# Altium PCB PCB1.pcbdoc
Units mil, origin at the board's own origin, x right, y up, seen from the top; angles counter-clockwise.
Board outline 1908.46 x 3230 mil, 2 copper layers (Top Layer, Bottom Layer); 17 components, 32 nets, 150 pads, 4 vias.
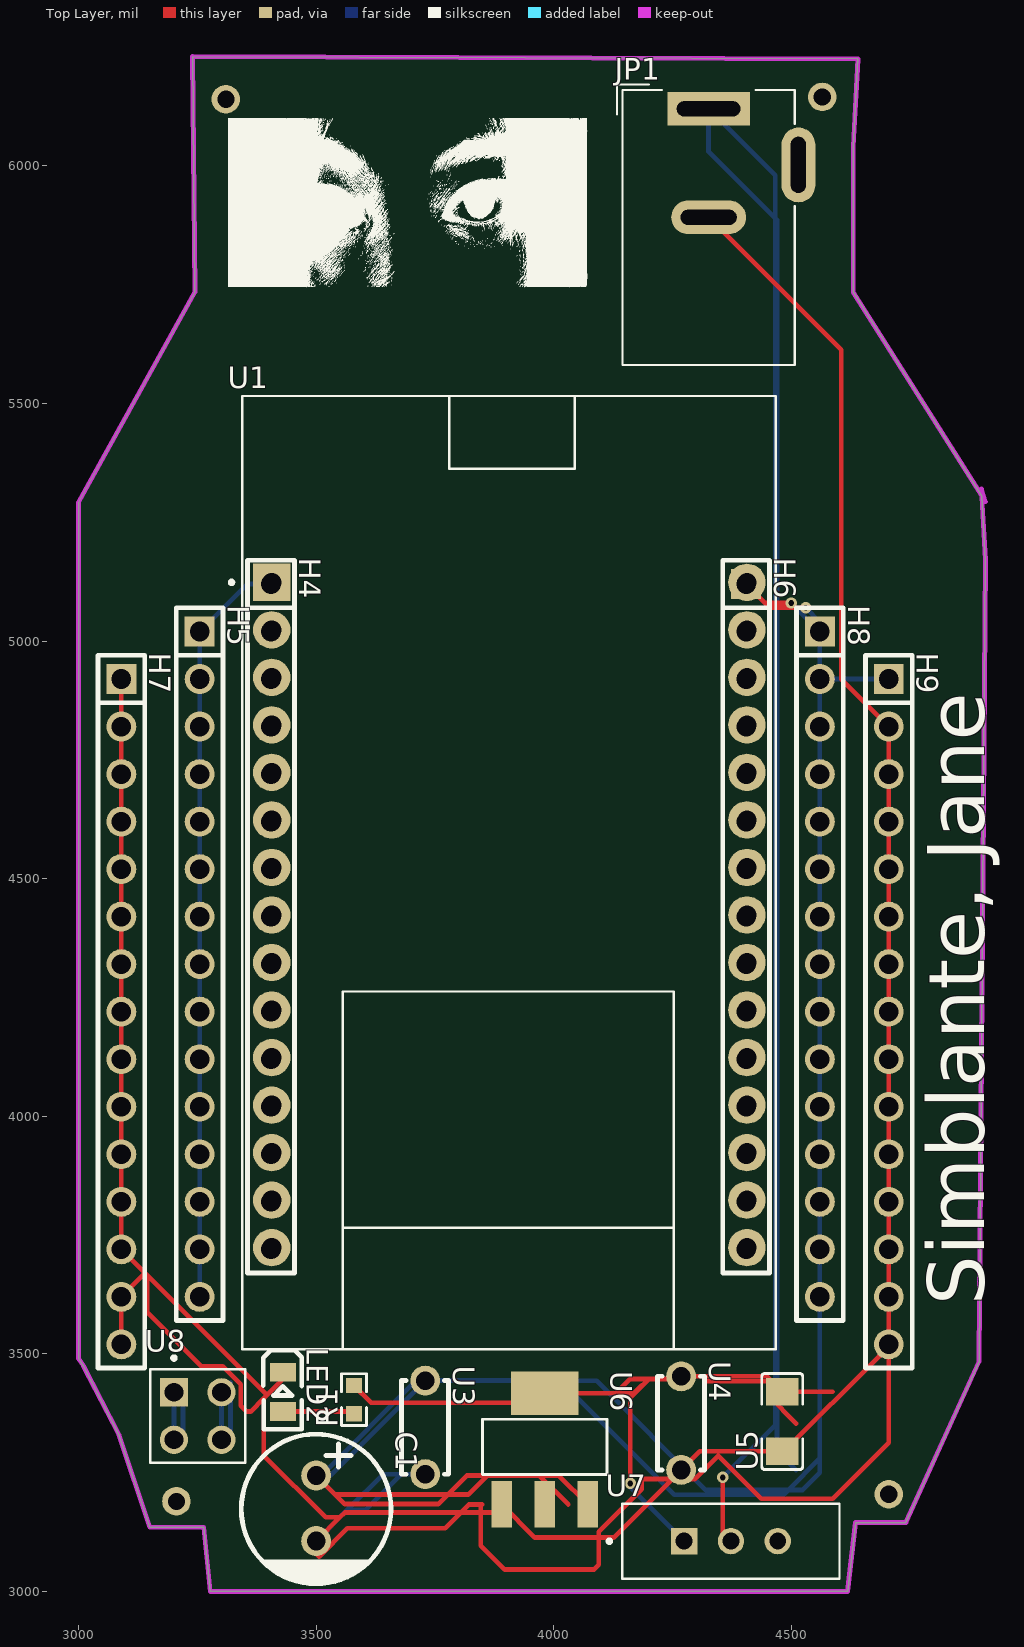
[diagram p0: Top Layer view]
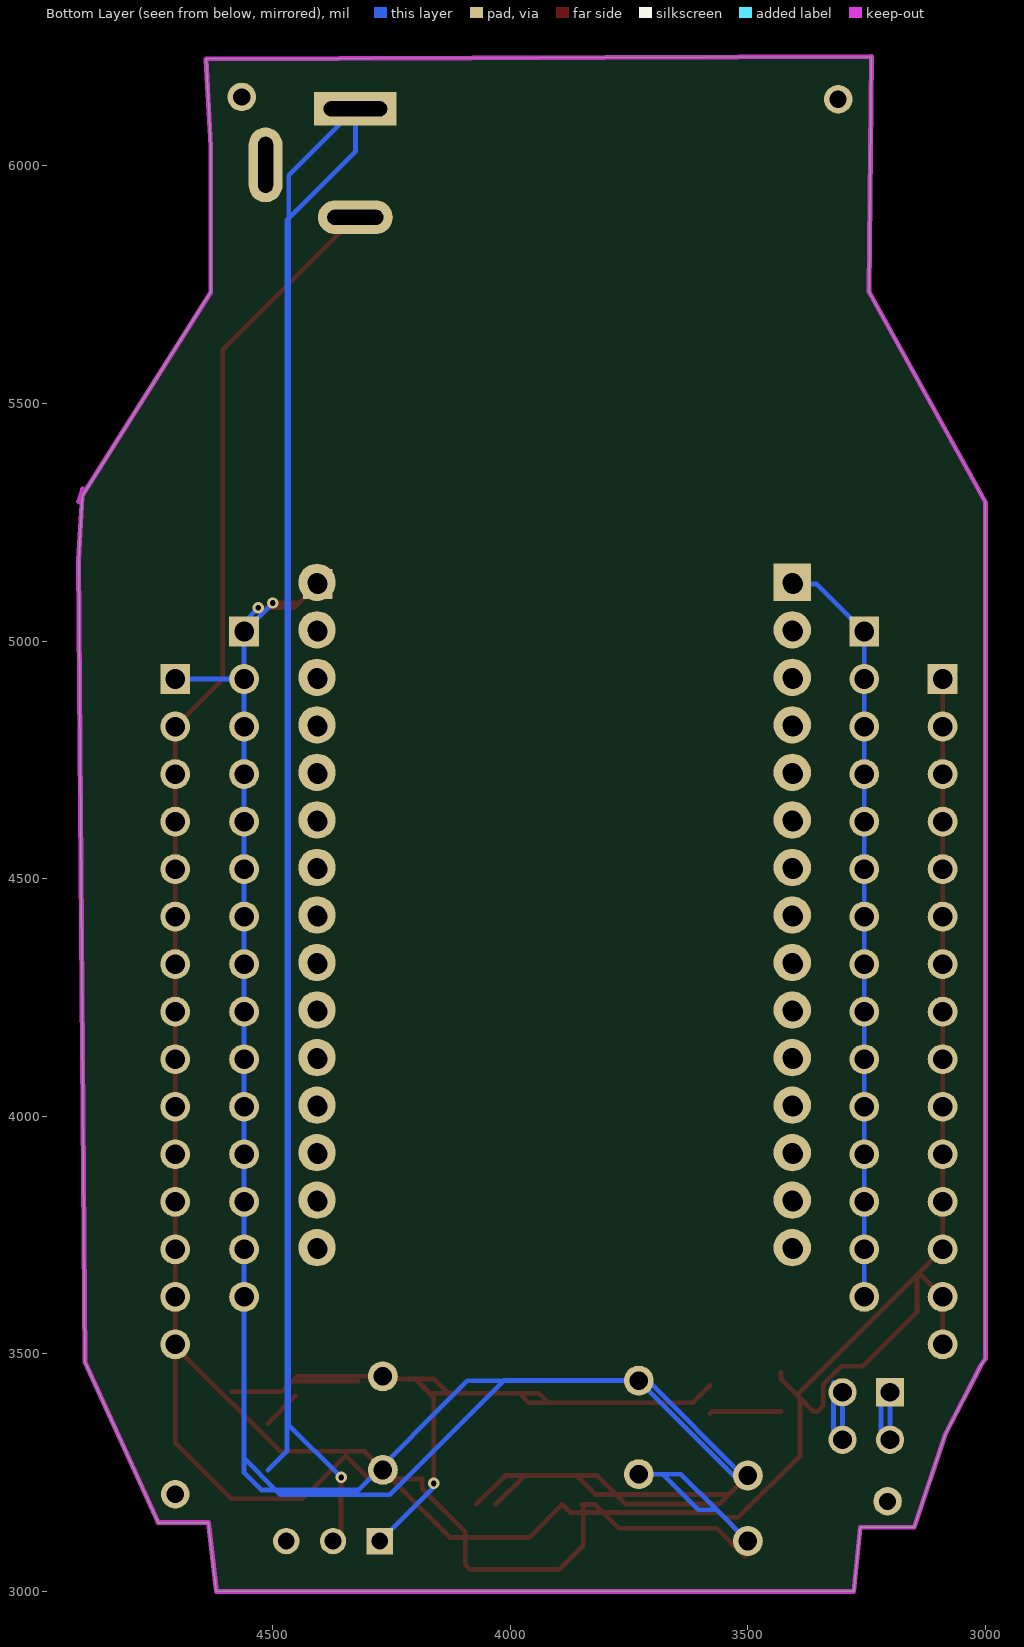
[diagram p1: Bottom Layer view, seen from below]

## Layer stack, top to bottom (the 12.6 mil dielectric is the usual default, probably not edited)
Top Layer: signal copper (thickness not stored)
Dielectric: dielectric 12.6, FR-4, Dk 4.8
Bottom Layer: signal copper (thickness not stored)

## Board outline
4908.46,5170.47 4900.84,5305.25 4630,5734.75 4630,6040 4640,6225 3240,6230 3245,5734.75 3000,5292.06 3000,3490 3010,3475 3085,3330 3149.93,3135 3263.45,3135 3277.42,3000 4618.27,3000 4635,3145 4741.01,3145 4895,3484.09

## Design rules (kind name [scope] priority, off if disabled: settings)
BoardOutlineClearance copperThickness1oz [All] p0: genericclearance=10 ignorepadtopadclearanceinfootprint=FALSE except(0: Arc-SplitContinuation Track-SplitContinuation SMDPad-SplitContinuation THPad-SplitContinuation Via-SplitContinuation Fill-SplitContinuation Poly-SplitContinuation Region-SplitContinuation Text-SplitContinuation; 6: Track-CutoutEdge SMDPad-CutoutEdge THPad-CutoutEdge Via-CutoutEdge Region-CutoutEdge; 11.8: Track-OutlineEdge SMDPad-OutlineEdge THPad-OutlineEdge Via-OutlineEdge Fill-OutlineEdge Region-OutlineEdge Poly-OutlineEdge Text-OutlineEdge Fill-CutoutEdge)
BoardOutlineClearance copperThickness2oz [All] p0: genericclearance=10 ignorepadtopadclearanceinfootprint=FALSE except(0: Arc-SplitContinuation Track-SplitContinuation SMDPad-SplitContinuation THPad-SplitContinuation Via-SplitContinuation Fill-SplitContinuation Poly-SplitContinuation Region-SplitContinuation Text-SplitContinuation; 6: Track-CutoutEdge SMDPad-CutoutEdge THPad-CutoutEdge Via-CutoutEdge Region-CutoutEdge; 11.8: Track-OutlineEdge SMDPad-OutlineEdge THPad-OutlineEdge Via-OutlineEdge Fill-OutlineEdge Region-OutlineEdge Poly-OutlineEdge Text-OutlineEdge Fill-CutoutEdge)
Clearance copperThickness1oz [(InNet('GND') OR InNet('+5V') OR InNet('+3V3') OR InNet('RXO') OR InNet('TXO') OR InNet('RX2') OR InNet('TX2') OR InNet('D22') OR InNet('D23') OR InNet('D25') OR InNet('D26') OR InNet('D27') OR InNet('D32') OR InNet('D33') OR InNet('D35') OR InNet('D34') OR InNet('EN') OR InNet('VP') OR InNet('VN') OR InNet('D2') OR InNet('D4') OR InNet('D5') OR InNet('D12') OR InNet('D13') OR InNet('D14') OR InNet('D15') OR InNet('D18') OR InNet('D19') OR InNet('D21') OR InNet('$1N4423') OR InNet('$1N7191') OR InNet('VCC'))] p1: gap=7 ignorepadtopadclearanceinfootprint=FALSE except(4: Track-Track; 6: Track-SMDPad SMDPad-SMDPad Track-THPad SMDPad-THPad THPad-THPad Track-Via SMDPad-Via THPad-Via Via-Via SMDPad-Fill THPad-Fill Via-Fill Fill-Fill Track-Region SMDPad-Region THPad-Region Via-Region Region-Region Track-Poly SMDPad-Poly THPad-Poly Via-Poly Fill-Poly Region-Poly Poly-Poly Track-Text SMDPad-Text THPad-Text Via-Text Fill-Text Region-Text Poly-Text Text-Text; 6.9: Track-Hole SMDPad-Hole THPad-Hole Via-Hole Fill-Hole Region-Hole Poly-Hole Text-Hole Sheet-Hole; 11.8: Track-Fill Fill-Region Track-Sheet SMDPad-Sheet THPad-Sheet Via-Sheet Fill-Sheet Region-Sheet Poly-Sheet Text-Sheet)
Clearance copperThickness2oz [All] p1: gap=7 ignorepadtopadclearanceinfootprint=FALSE except(6: Track-SMDPad SMDPad-SMDPad Track-THPad SMDPad-THPad THPad-THPad Track-Via SMDPad-Via THPad-Via Via-Via SMDPad-Fill THPad-Fill Via-Fill Fill-Fill Track-Region SMDPad-Region THPad-Region Via-Region Region-Region Track-Poly SMDPad-Poly THPad-Poly Via-Poly Fill-Poly Region-Poly Poly-Poly Track-Text SMDPad-Text THPad-Text Via-Text Fill-Text Region-Text Poly-Text Text-Text; 6.9: Track-Hole SMDPad-Hole THPad-Hole Via-Hole Fill-Hole Region-Hole Poly-Hole Text-Hole Sheet-Hole; 8: Track-Track; 11.8: Track-Fill Fill-Region Track-Sheet SMDPad-Sheet THPad-Sheet Via-Sheet Fill-Sheet Region-Sheet Poly-Sheet Text-Sheet)
DiffPairsRouting differentialPair [All] p1: maxuncoupledlength=10 minlimit=6 maxlimit=6 mostfreqgap=6 toplayer_minwidth=5 toplayer_prefwidth=10 toplayer_maxwidth=100 bottomlayer_minwidth=5 bottomlayer_prefwidth=10 bottomlayer_maxwidth=100
PasteMaskExpansion pasteMaskExpansion [All] p1: expansion=0
PlaneConnect innerPlane [All] p1: planeconnectstyle=Relief reliefexpansion=20 reliefentries=4 reliefconductorwidth=10 reliefairgap=10
PolygonConnect copperRegion [All] p1: connectstyle=Relief reliefentries=4 reliefconductorwidth=10 polygonreliefangle="90 Angle" airgapwidth=10
RoutingVias viaSize [All] p1: viastyle="Through Hole" holewidth=12.0078 minholewidth=11.811 maxholewidth=248.0314 width=24.0158 minwidth=19.685 maxwidth=393.7008
SolderMaskExpansion solderMaskExpansion [All] p1: useseparateexpansions=TRUE expansion=2 expansionbottom=2
Width copperThickness1oz [All] p1: maxlimit=100 minlimit=5 preferedwidth=10
Width copperThickness2oz [All] p1: maxlimit=100 minlimit=8 preferedwidth=10

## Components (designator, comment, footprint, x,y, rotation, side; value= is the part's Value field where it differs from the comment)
C1 "100uF" CAP-TH_BD8.0-P3.50-D0.6-FD_1 3500,3175 r270 top
H4 "HDR-M_2.54_1x15P" HDR-TH_15P-P2.54-V-M 3405,4420 r270 top
H5 "HDR-M_2.54_1x15P" HDR-TH_15P-P2.54-V-M 3255,4320 r270 top
H6 "HDR-M_2.54_1x15P" HDR-TH_15P-P2.54-V-M 4405,4420 r270 top
H7 "HDR-M_2.54_1x15P" HDR-TH_15P-P2.54-V-M 3090,4220 r270 top
H8 "HDR-M_2.54_1x15P" HDR-TH_15P-P2.54-V-M 4560,4320 r270 top
H9 "HDR-M_2.54_1x15P" HDR-TH_15P-P2.54-V-M 4705,4220 r270 top
JP1 "Connector_Barrel_Jack_MountingPin" Connector_BarrelJack:BarrelJack_Wuerth_6941xx301002 4325.88,6119.99 r0 top
LED2 "KT-0805W" LED0805-R-RD 3430,3420 r270 top
R1 "1K" R0603 3579.68,3403.61 r90 top
U1 "ESP32-DEVKIT-V1" MODULE_ESP32_DEVKIT_V1 3906.57,4512.7 r0 top
U3 "100nF" CAP-TH_L5.0-W2.5-P5.00-D1.0 3729.57,3345.28 r270 top
U4 "100nF" CAP-TH_L5.0-W2.5-P5.00-D1.0 4268.15,3354.25 r270 top
U5 "10nF" C1206 4480.83,3357.65 r90 top
U6 "AMS1117-5.0" SOT-223-3_L6.4-W3.5-P2.30-LS7.0-BR 3980.91,3300.39 r270 top
U7 "MINI-SPDT-SW" SW_MINI-SPDT-SW 4372.87,3105.91 r0 top
U8 "pin_2x2" TE_826656-2 3250.83,3369.21 r0 top

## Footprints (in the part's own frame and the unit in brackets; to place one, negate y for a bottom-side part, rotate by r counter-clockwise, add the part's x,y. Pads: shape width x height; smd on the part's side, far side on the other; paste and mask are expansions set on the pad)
C1206 [mm]
  rect 1.485x1.728 smd: 1(-1.593,0) 2(1.593,0)
  silkscreen extent -2.56,-1.09 2.56,1.09
CAP-TH_BD8.0-P3.50-D0.6-FD_1 [mm]
  round 1.6 hole 1: 1(-1.75,0) 2(1.75,0)
  silkscreen extent -3.96,-4 4.04,4
CAP-TH_L5.0-W2.5-P5.00-D1.0 [mm]
  round 1.6 hole 1: 1(-2.5,0) 2(2.5,0)
  silkscreen extent -2.5,-1.27 2.5,1.25
Connector_BarrelJack:BarrelJack_Wuerth_6941xx301002 [mm]
  rect 4.4x1.8 hole 0.8 slot 3.4 at 0 deg: 1(0,0)
  oval 4x1.8 hole 0.8 slot 3 at 0 deg: 2(0,-5.8)
  oval 1.8x4 hole 0.8 slot 3 at 90 deg: 3(4.8,-3)
  silkscreen extent -4.9,-13.7 4.6,1.3
HDR-TH_15P-P2.54-V-M [mm]
  rect 1.6x1.6 hole 1.05: 1(-17.78,0)
  round 1.6 hole 1.05: 2(-15.24,0) 3(-12.7,0) 4(-10.16,0) 5(-7.62,0) 6(-5.08,0) 7(-2.54,0) 8(0,0) 9(2.54,0) 10(5.08,0) 11(7.62,0) 12(10.16,0) 13(12.7,0) 14(15.24,0) 15(17.78,0)
  silkscreen extent -19.05,-1.25 19.05,1.25
LED0805-R-RD [mm]
  rect 1x1.4 smd: 1(1.05,0) 2(-1.05,0)
  silkscreen extent -2.22,-1.04 1.99,1.01
MODULE_ESP32_DEVKIT_V1 [mm]
  rect 2x2 hole 1.02: 1(-12.7,15.515)
  round 2 hole 1.02: 2(-12.7,12.975) 3(-12.7,10.435) 4(-12.7,7.895) 5(-12.7,5.355) 6(-12.7,2.815) 7(-12.7,0.275) 8(-12.7,-2.265) 9(-12.7,-4.805) 10(-12.7,-7.345) 11(-12.7,-9.885) 12(-12.7,-12.425) 13(-12.7,-14.965) 14(-12.7,-17.505) 15(-12.7,-20.045) 16(12.7,-20.045) 17(12.7,-17.505) 18(12.7,-14.965) 19(12.7,-12.425) 20(12.7,-9.885) 21(12.7,-7.345) 22(12.7,-4.805) 23(12.7,-2.265) 24(12.7,0.275) 25(12.7,2.815) 26(12.7,5.355) 27(12.7,7.895) 28(12.7,10.435) 29(12.7,12.975) 30(12.7,15.515)
  silkscreen extent -14.95,-25.48 14.23,25.48
R0603 [mil]
  rect 31.75x34.02 smd: 1(-29.66,0) 2(29.66,0)
  silkscreen extent -55,-26 55,26
SOT-223-3_L6.4-W3.5-P2.30-LS7.0-BR [mm]
  rect 2.5x1.1 smd: 1(2.97,-2.3) 2(2.97,0) 3(2.97,2.3)
  rect 2.34x3.6 smd: 4(-2.97,0)
  silkscreen extent -1.57,-3.33 1.37,3.33
SW_MINI-SPDT-SW [mm]
  rect 1.408x1.408 hole 0.9: 1(-2.5,0)
  round 1.408 hole 0.9: 2(0,0) 3(2.5,0)
  silkscreen extent -6.6,-2 5.8,2
TE_826656-2 [mm]
  rect 1.508x1.508 hole 1: 1(-1.27,1.27)
  round 1.508 hole 1: 2(1.27,1.27) 3(-1.27,-1.27) 4(1.27,-1.27)
  silkscreen extent -2.54,-2.5 2.54,3.2

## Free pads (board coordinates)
  round 60 hole 36: 1(3205.94,3189.68) 1(3310,6140) 2(4565,6145) 3(4705,3204.65)

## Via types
v1: diameter 24.02, hole 12.01, Top Layer to Bottom Layer, 4 vias

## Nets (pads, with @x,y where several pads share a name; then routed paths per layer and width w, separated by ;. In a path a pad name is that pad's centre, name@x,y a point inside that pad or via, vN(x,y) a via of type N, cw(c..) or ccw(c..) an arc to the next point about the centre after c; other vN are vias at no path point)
$1N4423: JP1.1 U7.2 | length 6065.9
  Top Layer w10: v1(4355.88,3239.99) 4355.88,3122.9 U7.2
  Bottom Layer w10: v1(4355.88,3239.99) 4465.88,3349.99 4465.88,5889.99 ; 4510,3255 4470,3295 4470,5885.87 4465.88,5889.99 ; 4465.88,5889.99 4325.88,6029.99 JP1.1 4465.88,5979.99 4465.88,5889.99
$1N7191: LED2.1 R1.1 | length 151.6
  Top Layer w10: LED2.1 3574.98,3378.65 R1.1
+3V3: H4.1 H5.1 H5.2 H5.3 H5.4 H5.5 H5.6 H5.7 H5.8 H5.9 H5.10 H5.11 H5.12 H5.13 H5.14 H5.15 U1.1 | length 1595.3
  Bottom Layer w10: H5.15 H5.14 H5.13 H5.12 H5.11 H5.10 H5.9 H5.8 H5.7 H5.6 H5.5 H5.4 H5.3 H5.2 H5.1 3355,5120 H4.1 U1.1
+5V: C1.1 H6.1 H8.1 H8.2 H8.3 H8.4 H8.5 H8.6 H8.7 H8.8 H8.9 H8.10 H8.11 H8.12 H8.13 H8.14 H8.15 H9.1 U1.30 U3.1 U6.3 | length 5852.3
  Top Layer w10: C1.1 3540,3203.9 ; 4030.55,3183.07 3969.72,3243.9 ; U6.3 4011.02,3243.9 3969.72,3243.9 ; U1.30 4405,5121.96 H6.1 4445,5080 ; v1(4500,5080) 4445,5080 ; v1(4530,5070) 4455,5070 4445,5080 ; 3540,3203.9 3560,3183.9 3756.7,3183.9 3776.7,3203.9 ; 3540,3203.9 3776.7,3203.9 ; 3776.7,3203.9 3820,3203.9 3860,3243.9 ; 3776.7,3203.9 3816.7,3243.9 3860,3243.9 ; 3860,3243.9 3969.72,3243.9
  Bottom Layer w10: C1.1 C1.1@3510.47,3243.9 ; v1(4500,5080) H8.1 ; v1(4530,5070) 4560,5040 H8.1 ; H9.1 H8.2 ; C1.1@3510.47,3243.9 3710,3443.43 U3.1@3729.29,3443.43 ; C1.1@3510.47,3243.9 3529.77,3243.9 U3.1@3729.29,3443.43 ; U3.1@3729.29,3443.43 4013.98,3443.43 ; U3.1@3729.29,3443.43 U3.1 4013.7,3443.7 4013.98,3443.43 ; 4013.98,3443.43 4090,3443.43 4320,3213.43 4493.43,3213.43 ; 4013.98,3443.43 4253.7,3203.7 4483.7,3203.7 4493.43,3213.43 ; 4493.43,3213.43 4523.43,3213.43 4560,3250 4560,3280 ; 4493.43,3213.43 4560,3280 ; 4560,3280 H8.15 H8.14 H8.13 H8.12 H8.11 H8.10 H8.9 H8.8 H8.7 H8.6 H8.5 H8.4 H8.3 H8.2 ; H8.2 H8.1
D2: H6.5 U1.4
D4: H6.6 U1.5
D5: H6.7 U1.8
D12: H6.8 U1.27
D13: H6.9 U1.28
D14: H6.10 U1.26
D15: H6.11 U1.3
D18: H6.12 U1.9
D19: H6.13 U1.10
D21: H6.14 U1.11 U8.1 U8.3 | length 200
  Bottom Layer w10: U8.3 U8.1 ; U8.3@3220,3340 U8.1@3220,3440
D22: H4.6 U1.14 U8.2 U8.4 | length 200
  Bottom Layer w10: U8.4 U8.2 ; U8.4@3320,3340 U8.2@3320,3440
D23: H4.7 U1.15
D25: H4.8 U1.23
D26: H4.9 U1.24
D27: H4.10 U1.25
D32: H4.11 U1.21
D33: H4.12 U1.22
D34: H4.14 U1.19
D35: H4.13 U1.20
EN: H6.2 U1.16
GND: C1.2 H4.15 H6.15 H7.1 H7.2 H7.3 H7.4 H7.5 H7.6 H7.7 H7.8 H7.9 H7.10 H7.11 H7.12 H7.13 H7.14 H7.15 H9.2 H9.3 H9.4 H9.5 H9.6 H9.7 H9.8 H9.9 H9.10 H9.11 H9.12 H9.13 H9.14 H9.15 JP1.2 LED2.2 U3.2 U4.2 U5.1 U6.1 | length 8930.7
  Top Layer w10: H7.15 H7.14 3136.1,3666.1 3143.9,3666.1 ; H7.1 H7.2 H7.3 H7.4 H7.5 H7.6 H7.7 H7.8 H7.9 H7.10 H7.11 H7.12 H7.13 3143.9,3666.1 ; 3400,3416.1 3393.9,3416.1 3143.9,3666.1 ; LED2.2 3430,3446.1 3390,3406.1 ; JP1.2 4605,5612.52 4605,4920 H9.2 H9.3 H9.4 H9.5 H9.6 H9.7 H9.8 H9.9 H9.10 H9.11 H9.12 H9.13 H9.14 H9.15 ; 3143.9,3666.1 3143.9,3588.3 3258.12,3474.09 3303.47,3474.09 3341.5,3436.06 3341.5,3390.71 3353.64,3378.57 3362.47,3378.57 3390,3406.1 ; 3390,3406.1 3390,3286.1 3520,3156.1 3550,3156.1 ; 3550,3156.1 C1.2 3496.14,3102.24 3496.14,3083.34 3506.14,3073.34 3565.63,3132.83 3771.46,3132.83 3804.72,3166.1 ; 3550,3156.1 3560,3166.1 3804.72,3166.1 ; 3804.72,3166.1 3846.46,3166.1 ; 3804.72,3166.1 3821.69,3183.07 3849.45,3183.07 3846.46,3180.07 3846.46,3166.1 ; 3846.46,3166.1 3846.46,3096.73 3897.13,3046.06 4084.61,3046.06 4094.61,3056.06 4094.61,3113.46 ; 3846.46,3166.1 3873,3166.1 U6.1 3960.36,3113.46 4094.61,3113.46 ; 4094.61,3113.46 4094.61,3125.24 4185,3215.63 4185,3236.57 U4.2@4248.9,3236.57 ; 4094.61,3113.46 4125.78,3113.46 U4.2@4248.9,3236.57 ; U4.2@4248.9,3236.57 4296.79,3236.57 4346.19,3285.97 4436.89,3195.28 4587.07,3195.28 4705,3313.21 H9.15 ; U4.2@4248.9,3236.57 U4.2 4307.27,3294.95 U5.1 4484.08,3294.95 4685.53,3496.4 H9.15
  Bottom Layer w10: C1.2 3565.63,3171.73 ; U3.2@3710,3246.57 3678.74,3246.57 3603.9,3171.73 3565.63,3171.73 ; U3.2 3640.75,3246.85 3565.63,3171.73
RX2: H4.4 U1.6
RXO: H4.2 U1.12
TX2: H4.5 U1.7
TXO: H4.3 U1.13
VCC: R1.2 U4.1 U5.2 U6.4 U7.1 | length 2269
  Top Layer w10: R1.2 3615.63,3397.32 ; v1(4160.91,3227.32) 4160.91,3407.32 4200.91,3447.32 ; 4185,3433.43 4168.5,3416.93 U6.4@3980.51,3416.93 ; 4319.65,3442.4 U5.2@4458.78,3442.4 ; U5.2@4452.05,3411.37 4510,3353.43 ; 4586.7,3420.35 U5.2 U5.2@4458.78,3442.4 ; 3615.63,3397.32 3616.02,3396.93 3920,3396.93 U6.4@3920.39,3397.32 ; 3615.63,3397.32 U6.4@3920.39,3397.32 ; U6.4@3920.39,3397.32 3960.91,3397.32 U6.4@3980.51,3416.93 ; U6.4@3920.39,3397.32 3940,3416.93 U6.4@3980.51,3416.93 ; U6.4@3980.51,3416.93 U6.4 4130.91,3417.32 4160.91,3447.32 4200.91,3447.32 ; 4200.91,3447.32 4262.79,3447.32 U4.1 4448.51,3452.68 U5.2@4458.78,3442.4
  Bottom Layer w10: v1(4160.91,3227.32) 4160.91,3219.45 U7.1
VN: H6.4 U1.18
VP: H6.3 U1.17
pads on no net: JP1.3 U1.2 U1.29 U6.2 U7.3

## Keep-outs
Board Outline Layer:
  lines w10: 4900.84,5305.25 4908.46,5293.15 4900,5320 4900.84,5305.25 ; 4900.84,5305.25 4908.46,5170.47 4895,3484.09 4741.01,3145 4635,3145 4618.27,3000 3277.42,3000 3263.45,3135 3149.93,3135 3085,3330 3010,3475 3000,3490 3000,5292.06 3245,5734.75 3240,6230 4640,6225 4630,6040 4630,5734.75 4900.84,5305.25

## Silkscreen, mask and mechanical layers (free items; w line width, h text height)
Top Silkscreen Layer:
  drawing of 3743 lines, arcs and shapes, not listed
  text "Simblante, Jane" at 4905.47,3602.6 h120 r90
